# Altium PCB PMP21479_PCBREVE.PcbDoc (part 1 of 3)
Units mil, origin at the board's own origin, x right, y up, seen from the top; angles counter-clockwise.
Board outline 1915.03 x 2932.53 mil, 4 copper layers (Top Layer, Signal Layer 1, Signal Layer 2, Bottom Layer), stack 39.6 mil thick; 137 components, 82 nets, 411 pads, 91 vias.
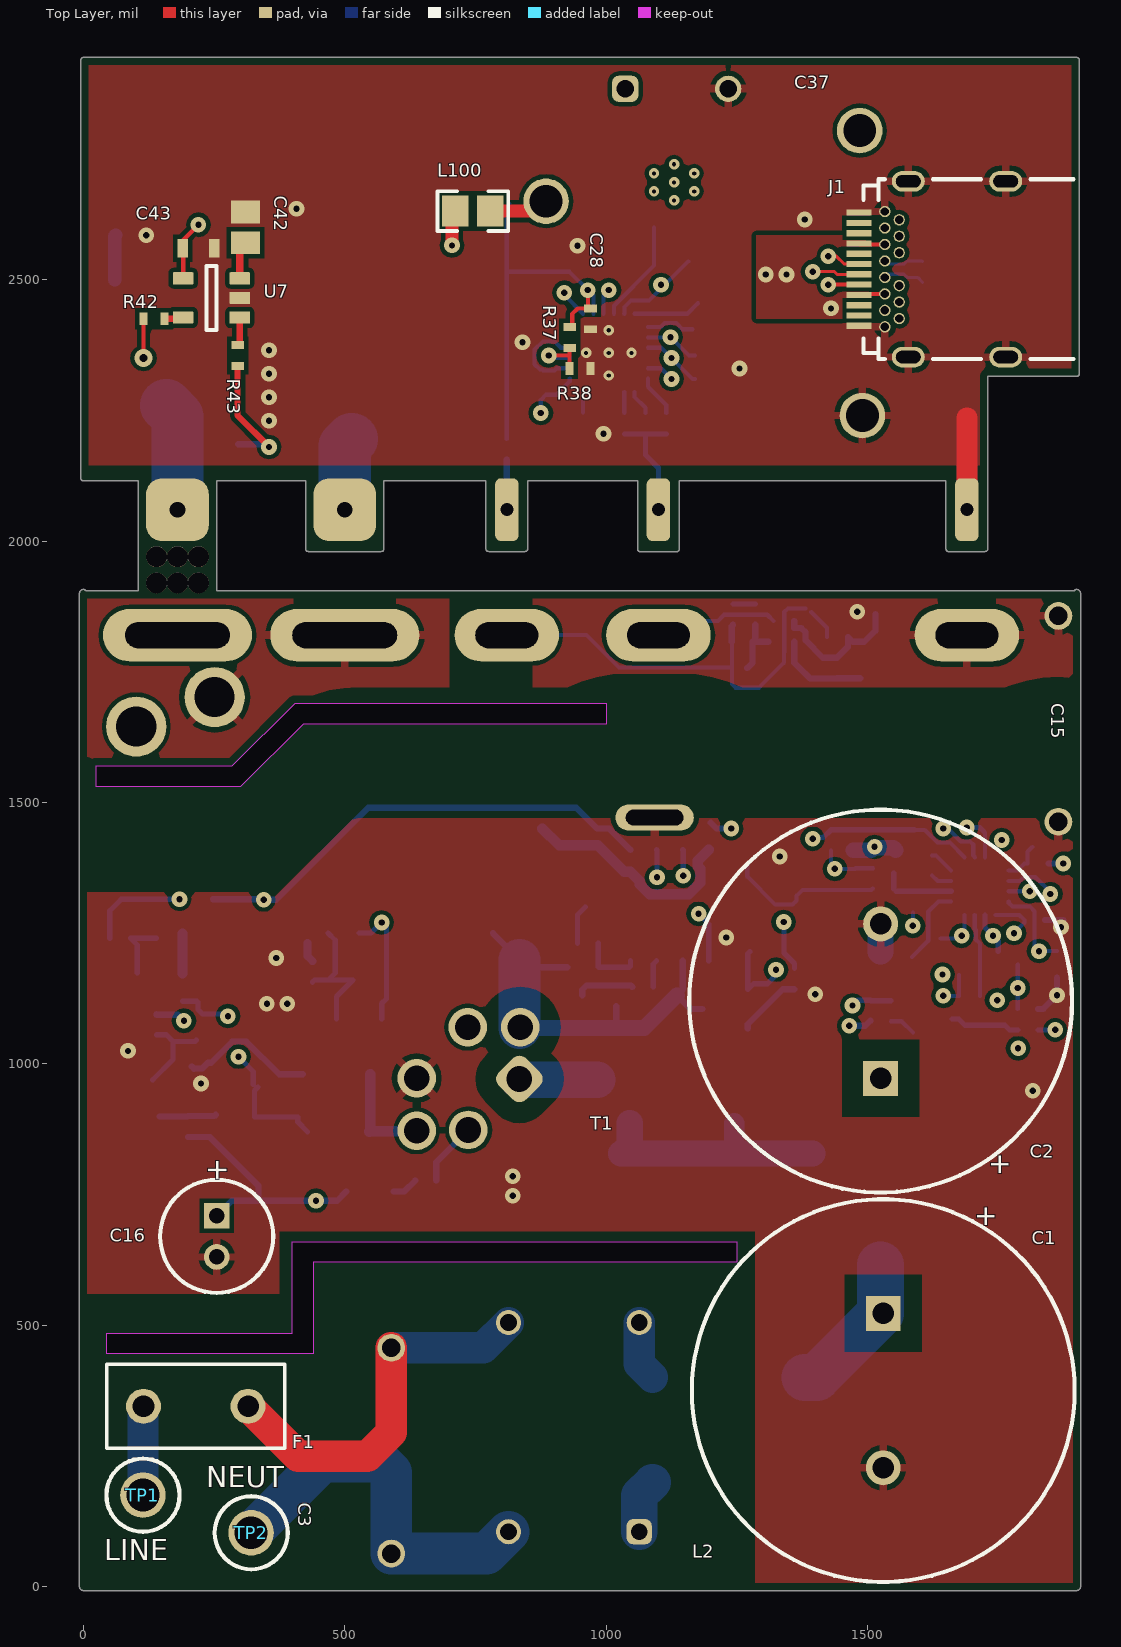
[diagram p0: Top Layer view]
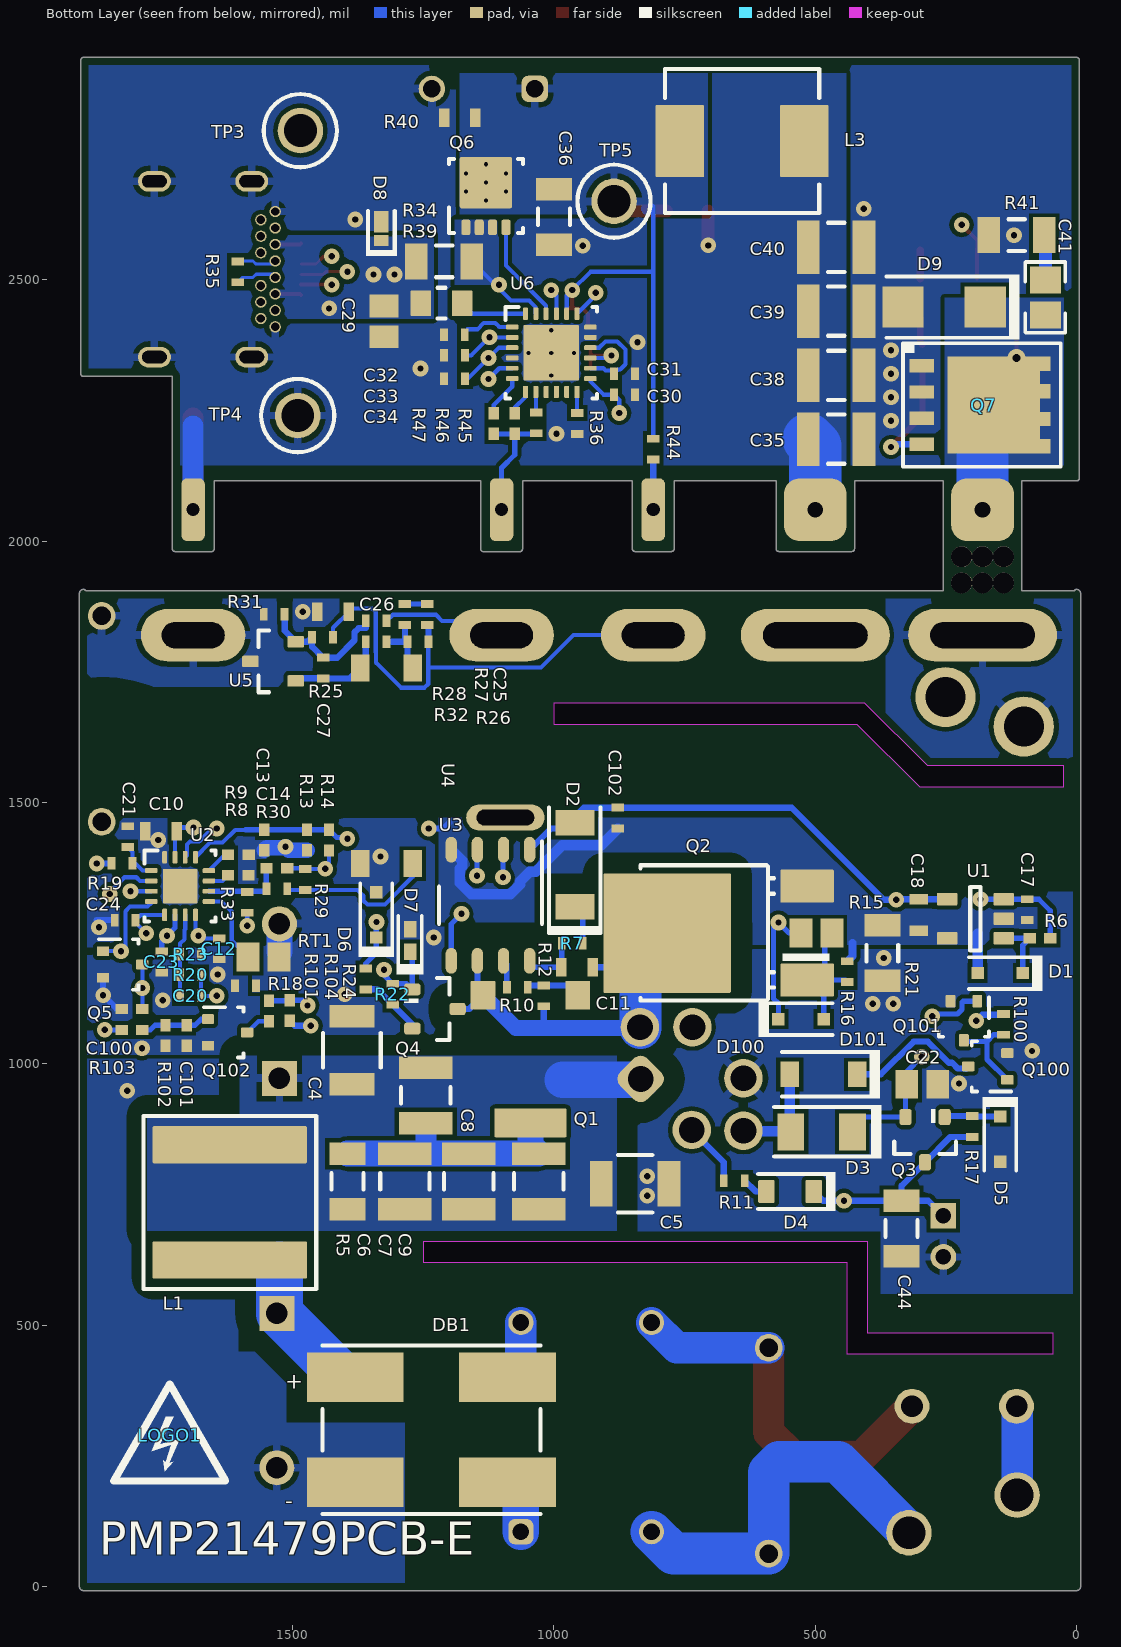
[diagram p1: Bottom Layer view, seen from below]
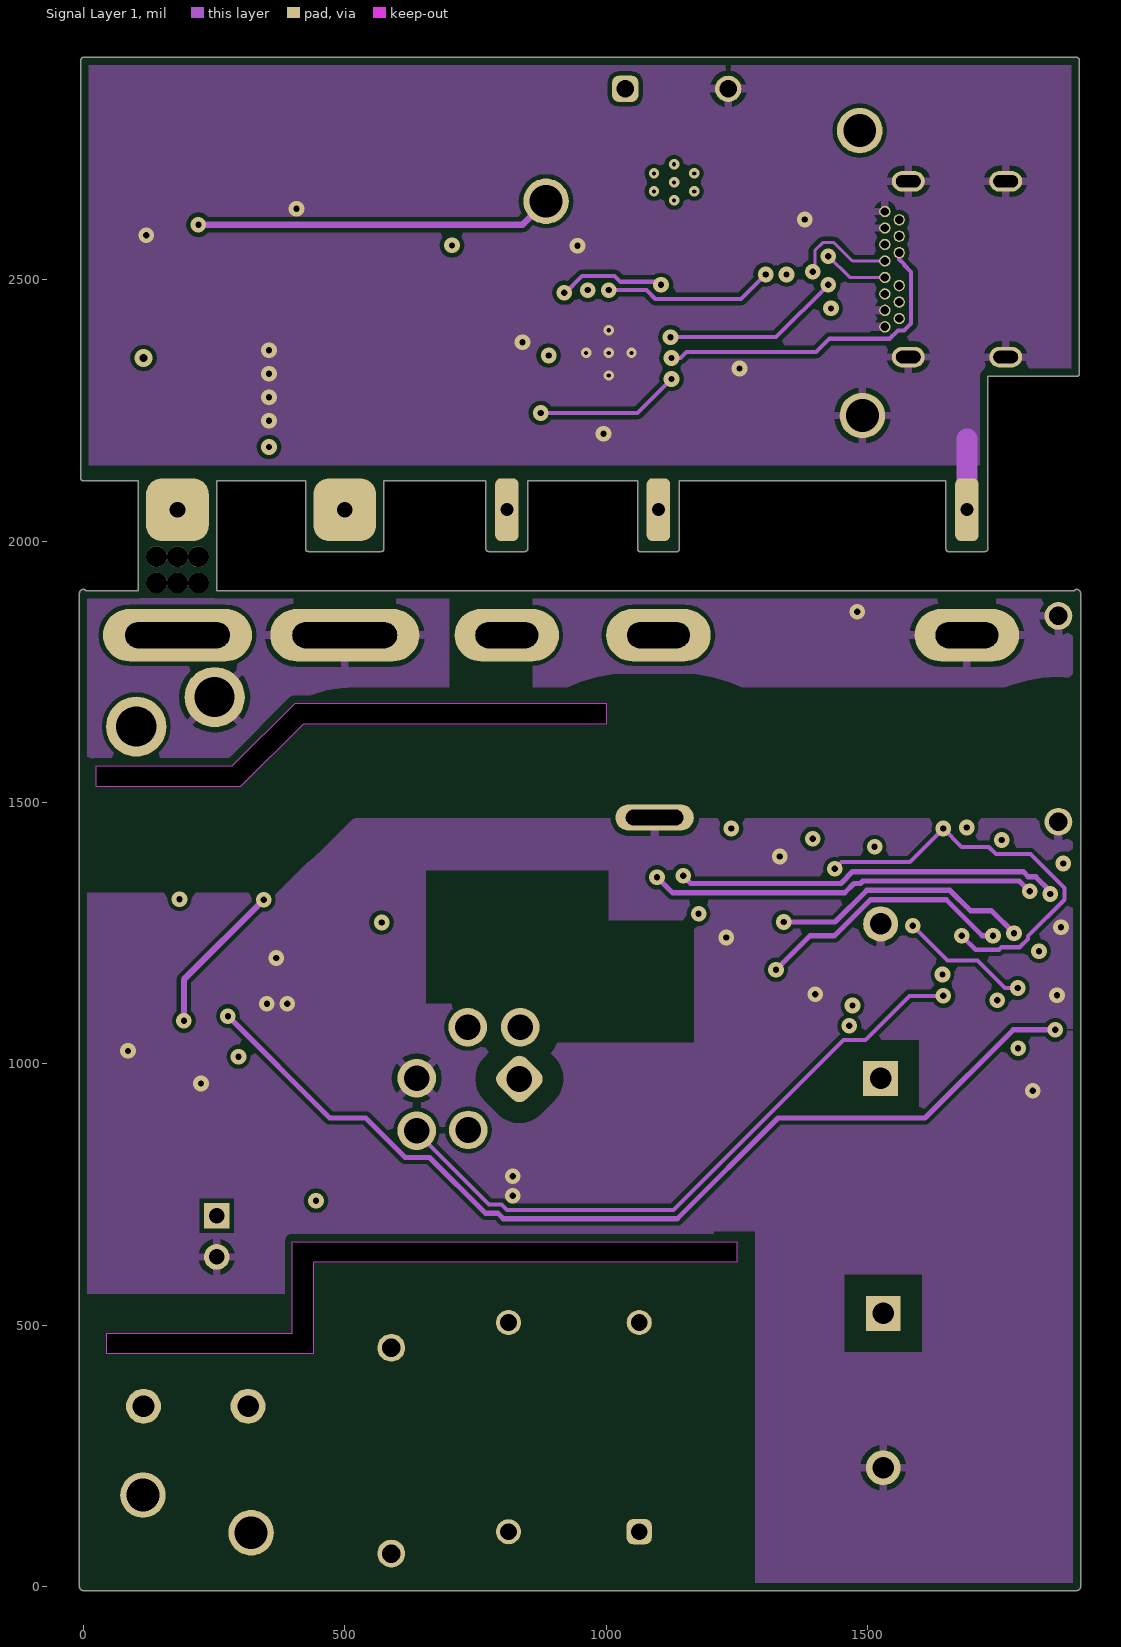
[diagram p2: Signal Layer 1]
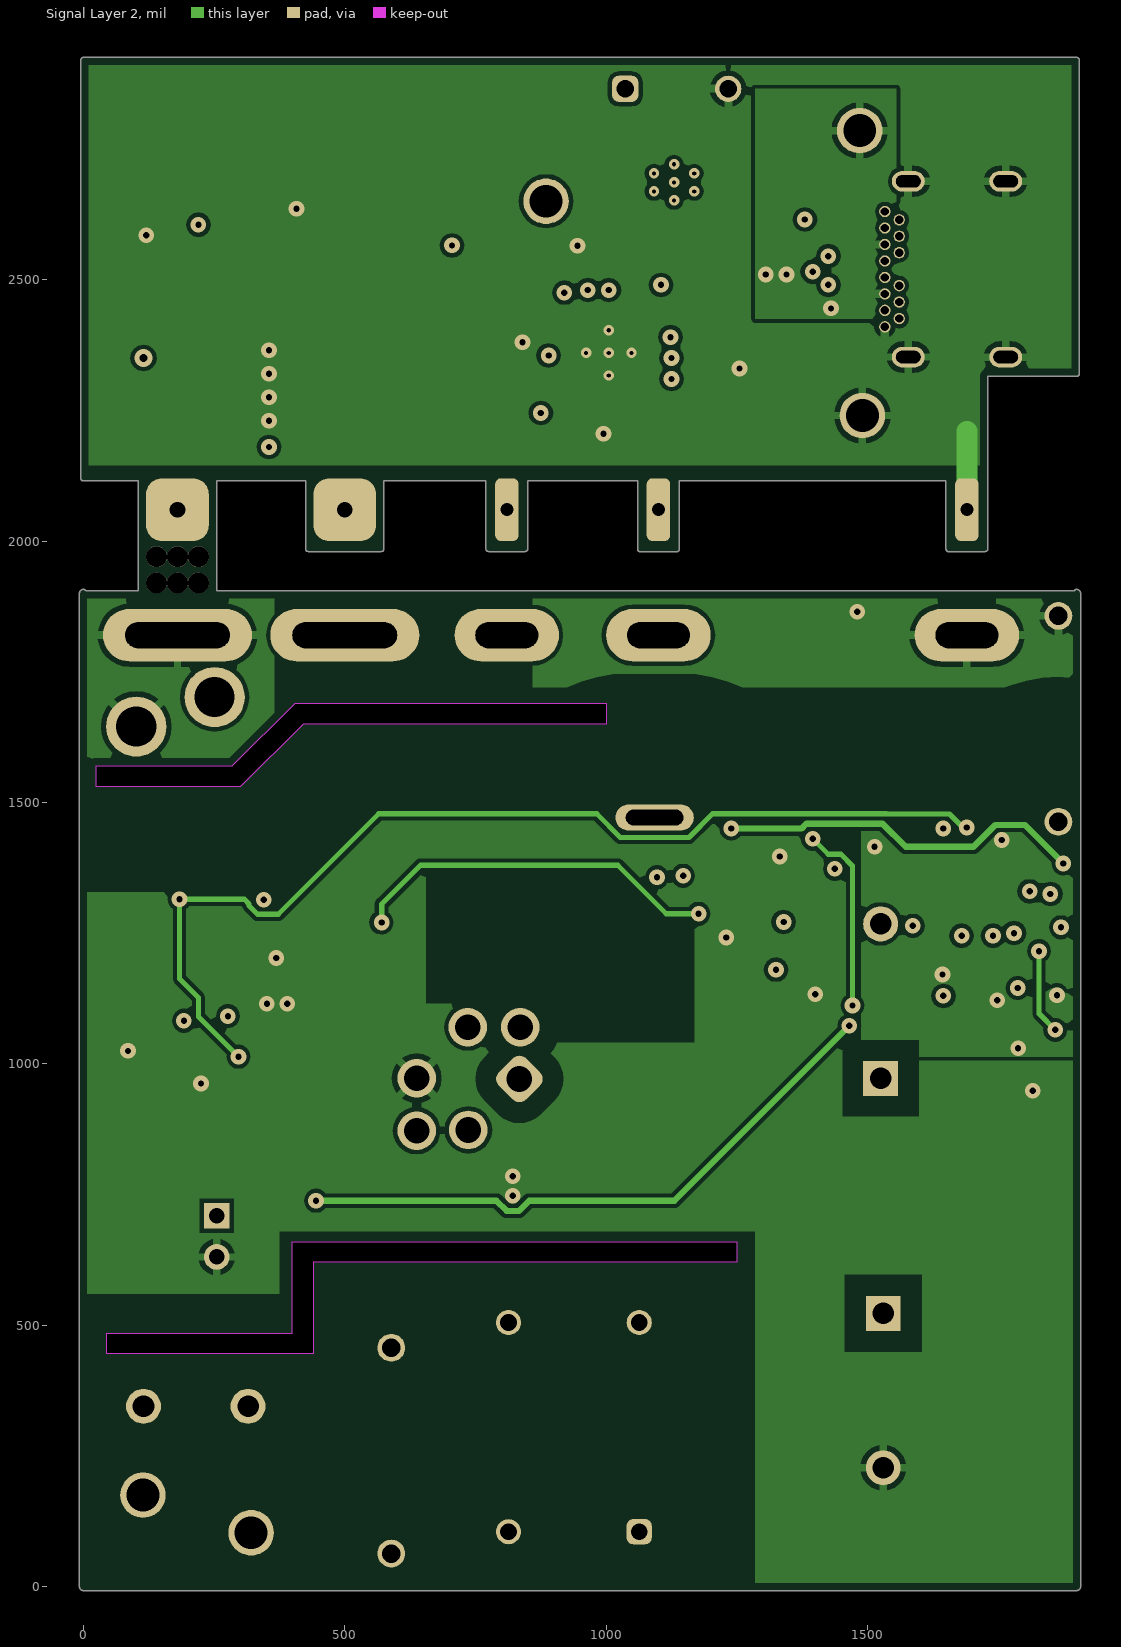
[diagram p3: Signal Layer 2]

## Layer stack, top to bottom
Top Solder: solder mask 0.4, Solder Resist, Dk 3.5
Top Layer: signal copper 1.4
Dielectric 1: prepreg 8, FR-4, Dk 4.2
Signal Layer 1: signal copper 1.4
Dielectric 2: core 18, FR-4, Dk 4.2
Signal Layer 2: signal copper 1.4
Dielectric 3: prepreg 8, FR-4, Dk 4.2
Bottom Layer: signal copper 1.4
Bottom Solder: solder mask 0.4, Solder Resist, Dk 3.5

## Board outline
0,-7.52 cw(c0,0) -7.52,0 -7.52,1900 cw(c0,1900) 0,1907.52 cw(c0,1902.5) 4.34,1905.02 104.98,1905.02 104.98,2114.98 0,2114.98 cw(c0,2120) -5.02,2120 -5.02,2920 cw(c0,2920) 0,2925.02 1900,2925.02 cw(c1900,2920) 1905.02,2920 1905.02,2320 cw(c1900,2320) 1900,2314.98 1730.02,2314.98 1730.02,1985 cw(c1725,1985) 1725,1979.98 1656.55,1979.98 cw(c1655,1984.76) 1649.98,1984.76 1649.98,2114.99 1140.02,2115.23 1140.02,1984.76 cw(c1135,1984.76) 1135,1979.74 1065,1979.74 cw(c1065,1984.76) 1059.98,1984.76 1059.98,2114.98 850.02,2114.98 850.02,1985 cw(c845,1985) 845,1979.98 775,1979.98 cw(c775,1985) 769.98,1985 769.98,2114.98 575.02,2114.98 575.02,1985 cw(c570,1985) 570,1979.98 430,1979.98 cw(c430,1985) 424.98,1985 424.98,2115.22 255.02,2114.99 255.02,1905.02 1895.66,1905.02 cw(c1900,1902.5) 1900,1907.52 cw(c1900,1900) 1907.52,1900 1907.52,0 cw(c1900,0) 1900,-7.52
cut-out: 25,1529.65 25,1570 285,1570 405,1690 1000,1690 1000,1649.65 420.35,1649.65 300.35,1529.65
cut-out: 45,445 45,485 400,485 400,660 1250,660 1250,620 440,620 440,445

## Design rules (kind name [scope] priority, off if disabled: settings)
AcuteAngle [All] p1: minimum=5.00000000000000E+0000 checktracksonly=FALSE
AssemblyTestPointUsage [All] p1: valid=2
BoardOutlineClearance BoardOutlineClearance_MountingHoles [OnCopper and InComponentClass('Mounting Holes')] p1: gap=25 ignorepadtopadclearanceinfootprint=FALSE
BoardOutlineClearance BoardOutlineClearance_Poly [OnCopper and InPoly] p2: gap=15 ignorepadtopadclearanceinfootprint=FALSE
BoardOutlineClearance [OnCopper and Not InComponentClass('Logo') and not InComponentClass('FiducialMark') and not InRegion(1000,500,4000,800)] p3: gap=15 ignorepadtopadclearanceinfootprint=FALSE
Clearance Isolation [InNetClass('Secondary') vs InNetClass('Primary')] p1: gap=250 ignorepadtopadclearanceinfootprint=FALSE
Clearance "High Voltage" [InNetClass('High Voltage') vs InNetClass('Primary')] p2: gap=40 ignorepadtopadclearanceinfootprint=FALSE
Clearance Clearance_Keepouts [((IsTrack Or IsArc) And Not InPoly) And IsFree and IsKeepOut vs ((IsTrack Or IsArc) And Not InPoly) And IsFree and IsKeepOut] p3: gap=0 ignorepadtopadclearanceinfootprint=FALSE
Clearance Clearance_Poly [InPolygon] p4: gap=8 ignorepadtopadclearanceinfootprint=FALSE except(0: Arc-Hole Track-Hole SMDPad-Hole THPad-Hole Via-Hole Fill-Hole Poly-Hole Region-Hole Text-Hole)
Clearance [All] p5: gap=7.87 ignorepadtopadclearanceinfootprint=FALSE except(0: Arc-Hole Track-Hole SMDPad-Hole THPad-Hole Via-Hole Fill-Hole Poly-Hole Region-Hole Text-Hole)
ComponentClearance ComponentClearance_MountingHoles_FiducialMarks [InComponentClass('Mounting Holes') vs InComponentClass('FiducialMark')] p1: gap=50 collisioncheckmode=3 verticalgap=10 showdistances=FALSE
ComponentClearance ComponentClearance_Shunt [InComponentClass('Header') vs InComponentClass('Shunt')] p2: gap=0 collisioncheckmode=3 verticalgap=0 showdistances=FALSE
ComponentClearance ComponentClearance_Logo [InComponentClass('Logo')] p3: gap=50 collisioncheckmode=3 verticalgap=10 showdistances=FALSE
ComponentClearance ComponentClearance_ScrewToNut [(HasFootprint('NY PMS 440 0025 PH')) vs (HasFootprint('Keystone_1902C'))] p4: gap=5 collisioncheckmode=3 verticalgap=10 showdistances=FALSE
ComponentClearance ComponentClearance_MountingHoles [InComponentClass('Mounting Holes')] p5: gap=250 collisioncheckmode=3 verticalgap=100000 showdistances=FALSE
ComponentClearance ComponentClearance_SmallPassives [HasFootprint('0201*') or HasFootprint('0402*') or HasFootprint('0508') or HasFootprint('0603*') or HasFootprint('0612') or HasFootprint('0805*') or HasFootprint('0815*') or HasFootprint('0830*') or HasFootprint('1206*') or HasFootprint('1210*') or HasFootprint('1808*') or HasFootprint('1812*') or HasFootprint('1825*') or HasFootprint('2010*') or HasFootprint('2220*') or HasFootprint('2225*') or HasFootprint('2512*') or HasFootprint('2728*') or HasFootprint('3518*') vs HasFootprint('0201*') or HasFootprint('0402*') or HasFootprint('0508') or HasFootprint('0603*') or HasFootprint('0612') or HasFootprint('0805*') or HasFootprint('0815*') or HasFootprint('0830*') or HasFootprint('1206*') or HasFootprint('1210*') or HasFootprint('1808*') or HasFootprint('1812*') or HasFootprint('1825*') or HasFootprint('2010*') or HasFootprint('2220*') or HasFootprint('2225*') or HasFootprint('2512*') or HasFootprint('2728*') or HasFootprint('3518*')] p6: gap=14.96 collisioncheckmode=3 verticalgap=10 showdistances=FALSE
ComponentClearance ComponentClearance_THtoSMT [IsThruComponent vs IsSMTComponent] p7: gap=15 collisioncheckmode=3 verticalgap=30 showdistances=FALSE
ComponentClearance ComponentClearance_THtoTH [IsThruComponent vs IsThruComponent] p8: gap=15 collisioncheckmode=3 verticalgap=30 showdistances=FALSE
ComponentClearance [All] p9: gap=15 collisioncheckmode=3 verticalgap=10 showdistances=FALSE
DiffPairsRouting [All] p1: maxlimit=100 minlimit=10 mostfreqgap=10 toplayer_minwidth=15 toplayer_maxwidth=15 toplayer_prefwidth=15 midlayer1_minwidth=15 midlayer1_maxwidth=15 midlayer1_prefwidth=15 midlayer2_minwidth=15 midlayer2_maxwidth=15 midlayer2_prefwidth=15 bottomlayer_minwidth=15 bottomlayer_maxwidth=15 bottomlayer_prefwidth=15 maxuncoupledlength=1000
FabricationTestPointUsage TestPointUsage [All] p1: valid=2 allowmultiple=FALSE
FabricationTestpoint Testpoint [All] p1: side=3 testpointundercomponent=TRUE minsize=40 maxsize=100 preferedsize=60 minholesize=0 maxholesize=40 preferedholesize=32 testpointgrid=1 allowsidetop=TRUE allowsidebottom=TRUE usegrid=TRUE gridtolerance=0.01
FanoutControl Fanout_LCC [IsLCC] p1: bgadir=Out bgaviamode=Centered fanoutstyle=Auto fanoutdirection=Alternating viagrid=1 // Fanout_LCC (Default Rule)
FanoutControl Fanout_BGA [IsBGA] p2: bgadir=Out bgaviamode=Centered fanoutstyle=Auto fanoutdirection=Alternating viagrid=1 // Fanout_BGA (Default Rule)
FanoutControl Fanout_Default [All] p4: bgadir=Out bgaviamode=Centered fanoutstyle=Auto fanoutdirection=Alternating viagrid=1 // Fanout_Default (Default Rule)
FanoutControl Fanout_Small [(CompPinCount < 5)] p5: bgadir=Out bgaviamode=Centered fanoutstyle=Auto fanoutdirection=OutThenIn viagrid=1 // Fanout_Small (Default Rule)
HoleSize [All] p1: absolutevalues=TRUE maxlimit=251 minlimit=7.87 maxpercent=80.000 minpercent=20.000
MinimumAnnularRing MinimumAnnularRing_ThermalPadVias [IsVia and InAnyComponent] p1: minimumring=5.91
MinimumAnnularRing [All] p2: minimumring=2.9
MinimumSolderMaskSliver MinimumSolderMaskSliver_Logo [InComponentClass('Logo') vs InComponentClass('Logo')] p1 off: minsoldermaskwidth=0.7
MinimumSolderMaskSliver [All] p2 off: minsoldermaskwidth=1
PlaneConnect [All] p1: planeconnectstyle=Direct reliefexpansion=10 reliefentries=4 reliefconductorwidth=10 reliefairgap=10
PolygonConnect [All] p1: thpad.connectstyle=Relief thpad.reliefconductorwidth=15 thpad.reliefentries=4 thpad.polygonreliefangle="90 Angle" thpad.airgapwidth=10 smdpad.connectstyle=Direct smdpad.reliefconductorwidth=10 smdpad.reliefentries=4 smdpad.polygonreliefangle="90 Angle" smdpad.airgapwidth=10 via.connectstyle=Direct via.reliefconductorwidth=10 via.reliefentries=4 via.polygonreliefangle="90 Angle" via.airgapwidth=10
RoutingVias ThermalPadVias [IsVia and InAnyComponent] p1: holewidth=7.87 width=19.68 viastyle="Through Hole" minholewidth=7.87 minwidth=19.68 maxholewidth=12.99 maxwidth=23.62
RoutingVias [All] p2: holewidth=16 width=34 viastyle="Through Hole" minholewidth=7.87 minwidth=26 maxholewidth=40 maxwidth=65
SilkToBoardRegionClearance [Not ((IsComment or IsDesignator) And (Hide <> 'False')) and not InRegion(1000,500,4000,800)] p1:
SilkToSilkClearance SilkToSilkClearance_Pb-FreeLogo [(HasFootprint('Pb-Free_Overlay_Medium') OR HasFootprint('Pb-Free_Overlay_Small')) vs (HasFootprint('Pb-Free_Overlay_Medium') OR HasFootprint('Pb-Free_Overlay_Small'))] p1: silktosilkclearance=0
SilkToSilkClearance [All] p2: silktosilkclearance=1
SilkToSolderMaskClearance SilkToComponentPadClearance [IsPad and InAnycomponent] p1: minsilkscreentomaskgap=0.5 clearancetoexposedcopper=TRUE
SilkToSolderMaskClearance "Silk to Solder Mask Opening" [All] p2: minsilkscreentomaskgap=0.5 clearancetoexposedcopper=FALSE
SolderMaskExpansion [All] p1: expansion=1.97
Width [All] p1: maxlimit=100 minlimit=6 preferedwidth=10 checkconnectedcopper=TRUE
15 further rules are at their usual default settings.

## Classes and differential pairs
net class Primary: ICGND NetC17_2 PGND
net class Secondary: SGND1 VDRN1 VN1
net class "High Voltage": NetC1_1 NetC6_2 NetC11_1 NetD2_1 NetQ1_1 NetR10_1 Vbulk Vswn
component class PMP21479_REVE_Secondary: C28 C29 C30 C31 C32 C33 C34 C35 C36 C37 C38 C39 C40 C41 C42 C43 D8 D9 J1 L3 L100 Q6 Q7 R34 R35 R36 R37 R38 R39 R40 R41 R42 R43 R44 R45 R46 R47 R49 R50 R51 R52 TP3 TP4 TP5 U6 U7 U8
component class PMP21479_REVE_Primary: C1 C2 C3 C4 C5 C6 C7 C8 C9 C10 C11 C12 C13 C14 C15 C16 C17 C18 C19 C20 C21 C22 C23 C24 C25 C26 C27 C44 C100 C101 C102 C? D1 D2 D3 D4 D5 D6 D7 D100 D101 D? DB1 F1 L1 L2 LOGO1 Q1 Q2 Q3 Q4 Q5 Q100 Q101 Q102 Q? R5 R6 R7 R8 R9 R10 R11 R12 R13 R14 R15 R16 R17 R18 R19 R20 R21 R22 R23 R24 R25 R26 R27 R28 R29 R30 R31 R32 R33 R100 R101 R102 R103 R104 R? RT1 T1 TP1 TP2 TP? U1 U2 U3 U4 U5 U?

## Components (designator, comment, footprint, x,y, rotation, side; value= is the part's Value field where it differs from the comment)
C1 "UCY2G560MHD3" UCY_1800x2000 1530,375 r270 top value=56uF
C2 "UCY2G560MHD3" UCY_1800x2000 1525,1120 r90 top value=56uF
C3 "890324023023" WCAP-FTX2_1300x700x1300 589,260 r270 top value=0.1uF
C4 "C1210C104KBRAC7800" 1210_280 1386.21,1025.74 r270 bottom value=0.1uF
C5 "C1210C104KBRAC7800" 1210_280 844.76,770.78 r0 bottom value=0.1uF
C6 "GRM32DR72E224KW01L" 1210_220L 1285,775 r90 bottom value=0.22uF
C7 "GRM32DR72E224KW01L" 1210_220L 1163.04,775 r90 bottom value=0.22uF
C8 "GRM32DR72E224KW01L" 1210_220L 1245,939.5 r270 bottom value=0.22uF
C9 "GRM32DR72E224KW01L" 1210_220L 1028.92,775 r90 bottom value=0.22uF
C10 "C1608X7R1E105K080AB" 0603S 1751.76,1445 r0 bottom value=1uF
C11 "GRM188R71E473KA01D" 0603S 955.79,1184.79 r180 bottom value=0.047uF
C12 "C1005X7R1H104K050BB" 0402S 1640,1220 r270 bottom value=0.1uF
C13 "GRM1555C1H101JA01D" 0402L 1553.89,1428.26 r270 bottom value=100pF
C14 "GRM1555C1H101JA01D" 0402L 1530,1374.02 r0 bottom value=100pF
C15 "DE1E3RA222MN4AN01F" DE1_900x400 1865,1659.84 r270 top value=2200pF
C16 "UPS2A4R7MDD1TD" UPW_500x1100 255,670 r270 top value=4.7uF
C17 "GRM155R71E104KE14D" 0402S 94.7,1294.91 r270 bottom value=0.1uF
C18 "C1608X7R1E105K080AB" 0603S 302.31,1284.93 r90 bottom value=1uF
C20 "GRM1555C1H3R3CA01D" 0402S 1695,1130 r0 bottom value=3.3pF
C21 "GJM1555C1H270JB01" 0402S 1815,1434.54 r90 bottom value=27pF
C22 "GRM21BC8YA106KE11L" 0805L 295.27,960.78 r0 bottom value=22uF
C23 "GRM155R71H222KA01D" 0402S 1750,1195 r270 bottom value=2200pF
C24 "GRM1555C1H240JA01D" 0402S 1820,1275 r180 bottom value=24pF
C25 "GRM155R71H183KA12D" 0402S 1242.59,1859.64 r90 bottom value=0.018uF
C26 "C1608X7R1E105K080AB" 0603S 1422.24,1864.5 r180 bottom value=1uF
C27 "GRM155R71H472KA01D" 0402S 1441.58,1757.01 r270 bottom value=4700pF
C28 "GRM155R71E104KE14D" 0402S 970,2425 r270 top value=0.1uF
C29 "GRM21BR6YA106KE43L" 0805L 1325,2420 r270 bottom value=10uF
C30 "GRM155R60J274KE01D" 0402S 865,2280 r180 bottom value=0.27uF
C31 "GRM155R71C104KA88D" 0402S 865,2320 r180 bottom value=0.1uF
C32 "GRM155R71C104KA88D" 0402S 1190.5,2394.75 r0 bottom value=0.1uF
C33 "GRM155R71H471KA01D" 0402S 1190,2355 r0 bottom value=470pF
C34 "GRM155R71H471KA01D" 0402S 1190,2310 r0 bottom value=470pF
C35 "GRM32ER71E226KE15L" 1210_270L 460,2195 r180 bottom value=22uF
C36 "GRM31MR71H224KA01L" 1206L 1000,2620 r270 bottom value=0.22uF
C37 "687AVG025MGBJ" AVG_1000x1200_HD 1135,2865 r0 top value=680uF
C38 "GRM32ER71E226KE15L" 1210_270L 460,2316.82 r180 bottom value=22uF
C39 "GRM32ER71E226KE15L" 1210_270L 460,2440 r180 bottom value=22uF
C40 "GRM32ER71E226KE15L" 1210_270L 460,2561.58 r180 bottom value=22uF
C41 "GRM21A5C2E101JW01D" 0805 60,2466.03 r90 bottom value=100pF
C42 "GRM21BR71E225KA73L" 0805L 310,2600 r270 top value=2.2uF
C43 "C1608X7R1E105K080AB" 0603S 220,2560 r0 top value=1uF
C44 "12061C104JAT2A" 1206L 335,685 r270 bottom value=0.1uF
C100 "GRM1555C1H150JA01D" 0402L 1806.83,1105 r0 bottom value=15pF
C101 "GRM1555C1H221JA01D" 0402L 1702.42,1053.97 r270 bottom value=220pF
C102 "GRM155R71E104KE14D" 0402S 877.65,1470 r270 bottom value=0.1uF
D1 "MMSZ5240BS-7-F" SOD-323 146.26,1173.62 r0 bottom value=10V
D2 "ES1JAF" SMAF 960,1380.41 r90 bottom value=600V
D3 "CSFMT104-HF" SOD-123H 487.99,870 r0 bottom value=200V
D4 "RFU02VSM8STR" TUMD2SM 548.19,755.78 r0 bottom value=800V
D5 "MMSZ5245BS-7-F" SOD-323 146.26,856.02 r270 bottom value=15V
D6 "CDSOD323-T18" SOD-323 1340,1285.1 r90 bottom value=18V
D7 "BZT52C22T-7" SOD-523 1275,1236.21 r90 bottom value=22V
D8 "NSR20F30NXT5G" DSN2_0603 1330,2600 r90 bottom value=30V
D9 "SMAJ100CA" SMA 253.74,2447.6 r0 bottom value=100V
D100 "BAS316,115" SOD-323 527.22,1085.59 r180 bottom value=100V
D101 "BAV21W-7-F" SOD-123 484.31,980 r0 bottom value=200V
DB1 "Z4DGP406L-HF" Z4-D 1234.23,300 r180 bottom value=600V
F1 "3.15A" FUSE_392 215,345 r180 top
J1 "632 723 300 011" Wurth_632_723_300_011 1900,2520 r90 top
L1 "NRS8030T220MJGJ" NRS8030 1620,735 r90 bottom value=22uH
L2 "RLTI-1301" Renco_RLTI-1301 938.19,305 r180 top value=1.3mH
L3 "0630CDMCCDS-R33MC" 0630CDMCCDS 640,2765 r0 bottom value=330nH
L100 "LBR2012T1R0M" 0805 745,2631.14 r0 top value=1uH
LOGO1 "DANGER HIGH VOLTAGE" IEC_HighVoltage_Small 1735,290 r180 bottom
Q1 "IPN70R2K0P7SATMA1" PG-SOT223 1045,1009.15 r270 bottom value=700V
Q2 "IPD60R280P7SAUMA1" DPAK 649.5,1250 r0 bottom value=600V
Q3 "BSS123" SOT-23L 290,855 r270 bottom value=100V
Q4 "BSS126H6327XTSA2" SOT-23L 1227.5,1104.92 r180 bottom value=600V
Q5 "NX3020NAKW,115" SOT-323 1825,1190 r180 bottom value=30V
Q6 "CSD17575Q3" DQG0008A 1130,2660 r90 bottom value=30V
Q7 "BSC093N15NS5ATMA1" PG-TDSON-8 185,2260 r180 bottom value=150V
Q100 "2N7002KW" SOT-323 170,995 r0 bottom value=60V
Q101 "2N7002KW" SOT-323 215.7,1082.4 r270 bottom value=60V
Q102 "2N7002KW" SOT-323 1624.17,1060 r180 bottom value=60V
R5 "CRCW12063M30JNEA" 1206L 1395,775 r270 bottom value=3.3Meg
R6 "RC0402FR-07100KL" 0402L 70.32,1240.12 r180 bottom value=100k
R7 "CRCW04024R70JNED" 0402S 965,1230.73 r0 bottom value=4.7
R8 "CRCW0402200KFKED" 0402L 1603.8,1360.52 r0 bottom value=200k
R9 "CRCW0402130KFKED" 0402L 1603.67,1400 r0 bottom value=130k
R10 "CRCW040215R0JNED" 0402S 1070,1146.9 r180 bottom value=15
R11 "CRCW04020000Z0ED" 0402S 655,776.69 r180 bottom value=0
R12 "CRCW040210K0JNED" 0402S 1019.18,1130 r90 bottom value=10k
R13 "CRCW040248K7FKED" 0402L 1472.39,1428.13 r90 bottom value=48.7k
R14 "CRCW0402200KFKED" 0402L 1430,1427.88 r270 bottom value=200k
R15 "CRCW080547R0JNEA" 0805L 497.69,1250 r180 bottom value=47
R16 "CRCW040210K0JNED" 0402S 438.51,1176.22 r270 bottom value=10k
R17 "CRCW04021M00JNED" 0402S 200,880 r90 bottom value=1.0Meg
R18 "CRCW04020000Z0ED" 0402S 1589.76,1149.07 r0 bottom value=0
R19 "CRCW04021K78FKED" 0402S 1826.14,1383.31 r0 bottom value=1.78k
R20 "CRCW040256K2FKED" 0402S 1695,1170 r180 bottom value=56.2k
R21 "ERJ-8BSFR15V" 1206L 371.87,1211.82 r90 bottom value=0.15
R22 "ERJ-2RKF1373X" 0402S 1308.42,1133.28 r90 bottom value=137k
R23 "CRCW040213K3FKED" 0402S 1695,1210 r0 bottom value=13.3k
R24 "CRCW0402118RFKED" 0402S 1360,1162.4 r270 bottom value=118
R25 "ERJ-2RKF1503X" 0402S 1442.55,1816.15 r180 bottom value=150k
R26 "CRCW04023K01FKED" 0402S 1260,1807.5 r180 bottom value=3.01k
R27 "CRCW0402150RFKED" 0402S 1285,1859.64 r90 bottom value=150
R28 "CRCW040224K9FKED" 0402S 1340,1847.15 r0 bottom value=24.9k
R29 "CRCW04021M00JNED" 0402S 1476.03,1352.58 r90 bottom value=1.0Meg
R30 "CRCW040239K2FKED" 0402S 1530,1335 r180 bottom value=39.2k
R31 "ERJ-2RKF1503X" 0402S 1535,1860 r0 bottom value=150k
R32 "CRCW040215K0FKED" 0402S 1340,1807.6 r180 bottom value=15.0k
R33 "CRCW0402511KFKED" 0402S 1586.76,1308.97 r90 bottom value=511k
R34 "WSL12065L000FEA" 1206L 1210,2535 r180 bottom value=0.005
R35 "CRCW0402100RJNED" 0402S 1605,2515 r90 bottom value=100
R36 "CRCW0402100KFKED" 0402S 955,2225 r90 bottom value=100k
R37 "CRCW0402140KFKED" 0402S 930.2,2389.53 r90 top value=140k
R38 "CRCW040286K6FKED" 0402S 950,2330 r180 top value=86.6k
R39 "RG2012P-121-B-T5" 0805_HV1 1215,2455 r0 bottom value=120
R40 "CRCW060310M0JNEA" 0603S 1180,2809.8 r180 bottom value=10Meg
R41 "CRCW12061K00JNEA" 1206L 115,2585 r180 bottom value=1.0k
R42 "CRCW040210R0JNED" 0402S 135,2425 r180 top value=10
R43 "CRCW040210R0JNED" 0402S 295,2355 r270 top value=10
R44 "RC0402JR-070RL" 0402S 810,2175.79 r270 bottom value=0
R45 "RC0402JR-070RL" 0402S 1033.58,2226.03 r270 bottom value=0
R46 "CRCW040269K8FKED" 0402L 1075,2225 r90 bottom value=69.8k
R47 "CRCW040215K0FKED" 0402L 1115,2225 r90 bottom value=15.0k
R100 "CRCW040210K0JNED" 0402S 140,1075.5 r90 bottom value=10k
R101 "CRCW0402100KFKED" 0402L 1545,1101.18 r90 bottom value=100k
R102 "CRCW0402200KFKED" 0402L 1742.95,1053.97 r90 bottom value=200k
R103 "CRCW0402301KFKED" 0402L 1806.83,1064.63 r0 bottom value=301k
R104 "CRCW04021M00FKED" 0402L 1505.5,1102.13 r270 bottom value=1.00Meg
RT1 "NCP21WF104J03RA" 0805L 1555.47,1204.4 r180 bottom value=100k
T1 "RLTI-1273" Renco_RLTI-1273 486.1,1221.43 r225 top locked value=110uH
TP1 "LINE" Keystone5011 114,175 r270 top
TP2 "NEUTRAL" Keystone5012 321,103 r270 top
TP3 "VBUS" Keystone5010 1485,2785 r180 bottom
TP4 "SGND" Keystone5011 1490,2240 r180 bottom
TP5 "Vout" Keystone5010 885,2650 r180 bottom
U1 "TPS7B4250QDBVRQ1" DBV0005A_N 193.75,1277.52 r0 bottom
U2 "UCC28780RTER" RTE0016C_NV 1715,1340 r180 bottom
U3 "UCC27710DR" D0008B_L 1121.32,1303.36 r270 bottom
U4 "VOL618A-2T" SOP254P1020X230-4 1320,1570 r270 bottom
U5 "ATL431AIDBZR" DBZ0003A_L 1537.19,1769.87 r0 bottom
U6 "TPS25740BRGER" RGE0024H 1005,2360 r180 bottom
U7 "UCC24612-2DBVT" DBV0005A_N 245,2465 r180 top

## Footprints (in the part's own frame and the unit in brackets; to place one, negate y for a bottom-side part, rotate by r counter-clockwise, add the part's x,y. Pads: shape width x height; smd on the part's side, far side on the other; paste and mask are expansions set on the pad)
0402L [mm] "0402 from SM-752 data"
  rect 0.6x0.5 smd: 1(-0.5,0) 2(0.5,0)
  body extent -0.55,-0.3 0.55,0.3, height 0.6
0402S [mil] "Based on C0402S footprint from PADS legacy"
  rect 15x24 smd: 1(-20,0) 2(20,0)
  body extent -22,-12 22,12, height 24
0603S [mil]
  rect 20x35 smd: 1(-30,0) 2(30,0)
  body extent -34,-19 34,19, height 39
0630CDMCCDS [mm] "SMD, 2-Leads, Body 7x6.6mm"
  rrect4% 2.35x3.5 smd: 1(-3.025,0) 2(3.025,0)
  silkscreen extent -3.75,-3.5 3.75,3.5, body extent -3.65,-3.4 3.65,3.4, height 3
0805 [mm] "0805 from SM-752 data"
  rect 1.3x1.5 smd: 1(-0.85,0) 2(0.85,0)
  silkscreen extent -1.72,-0.97 1.72,0.97, body extent -1.1,-0.72 1.1,0.72, height 1.45
0805_HV1 [mm] "Custom footprint based on analyzing multiple manufacturer recommendations"
  rrect10% 1x1.25 smd: 1(-1,0) 2(1,0)
  silkscreen extent -0.2,-0.75 0.2,0.75, body extent -1.1,-0.72 1.1,0.73, height 1.45
0805L [mm] "0805 from SM-752 data"
  rect 1.1x1.4 smd: 1(-0.75,0) 2(0.75,0)
  body extent -1.1,-0.72 1.1,0.72, height 1.45
1206L [mm] "1206 from SM-752 data"
  rect 1.1x1.75 smd: 1(-1.35,0) 2(1.35,0)
  silkscreen extent -0.4,-0.77 0.4,0.77, body extent -1.7,-0.9 1.7,0.9, height 1.35
1210_220L [mm] "1210"
  rect 1.1x2.6 smd: 1(-1.35,0) 2(1.35,0)
  silkscreen extent -0.4,-1.2 0.4,1.2, body extent -1.7,-1.35 1.7,1.35, height 2.2
1210_270L [mm] "1210"
  rect 1.1x2.6 smd: 1(-1.35,0) 2(1.35,0)
  silkscreen extent -0.4,-1.2 0.4,1.2, body extent -1.7,-1.35 1.7,1.35, height 2.7
1210_280 [mm] "SMD, 2-Leads, Body 3.6x2.8mm, Height 2.8mm"
  rect 1.1x2.2 smd: 1(-1.65,0) 2(1.65,0)
  silkscreen extent -0.84,-1.4 0.84,1.4, body extent -1.8,-1.4 1.8,1.4, height 2.8
AVG_1000x1200_HD [mm] "TH, 2-Leads, Dia 10mm, Pin Spacing 5mm"
  rrect50% 1.275x1.275 hole 0.85: 1(-2.5,0)
  round 1.275 hole 0.85: 2(2.5,0)
  body extent -5.25,-15.25 5.25,0.31, height 10.5
D0008B_L [mm] "SOIC, 8-Leads, Body 4.9x3.9mm, Pitch 1.27mm, IPC High Density"
  oval 1.25x0.55 smd: 1(-2.7,1.905) 2(-2.7,0.635) 3(-2.7,-0.635) 4(-2.7,-1.905) 5(2.7,-1.905) 6(2.7,-0.635) 7(2.7,0.635) 8(2.7,1.905)
  silkscreen extent -3.1,-2.5 0.9,2.5, body extent -3,-2.45 3,2.45, height 1.63
DBV0005A_N [mm] "SOT23, 5-Leads, Body 2.9x1.6mm, Pitch 0.95mm, Lead Span 2.8mm, IPC Medium Density"
  rrect17% 1x0.6 smd: 1(-1.375,0.95) 2(-1.375,0) 3(-1.375,-0.95) 4(1.375,-0.95) 5(1.375,0.95)
  silkscreen extent -0.25,-1.55 0.25,1.55, body extent -1.42,-1.46 1.42,1.46, height 1.09
DBZ0003A_L [mm] "SOT23, 3-Leads, Body 2.9x1.3mm, Pitch 0.95mm, Lead Span 2.4mm, IPC High Density"
  rrect18% 0.8x0.55 smd: 1(-1.1,0.95) 2(-1.1,-0.95) 3(1.1,0)
  silkscreen extent 0.2,-1.5 0.7,1.5, body extent -1.26,-1.46 1.26,1.46, height 0.98
DE1_900x400 [mm] "TH, 2-Leads, Dia 9mm, Lead Spacing 10mm"
  round 1.35 hole 0.9: 1(-5,0) 2(5,0)
  body extent -5.3,-2 5.3,2, height 11.5
DPAK [mm] "D-PAK, 3-Pads, Body 6.22x6.73mm (max), TO-252AA using nominal STEP model"
  rrect6% 2.6x1.6 smd: 1(-3.4,2.28) 3(-3.4,-2.28)
  rrect2% 6.2x5.8 smd paste-2.9: 4(3.4,0)
  silkscreen extent -4.5,-3.3 4.7,3.28, body extent -3.86,-3.29 5.84,3.29, height 2.48
DQG0008A [mm] "SMD, 8-Leads, Body 3.3x3.3mm, Pitch 0.65mm"
  rrect45% 0.75x0.44 smd paste-0.05 mask-0.05: 1(-1.525,0.975) 2(-1.525,0.325) 3(-1.525,-0.325) 4(-1.525,-0.975) 5(1.525,-0.975) 6(1.525,-0.325) 7(1.525,0.325) 8(1.525,0.975)
  rrect15% 0.676x1.125 on Bottom Paste: 9(-0.212,-0.663) 9(-0.212,0.662) 9(0.664,-0.663) 9(0.664,0.662)
  rrect6% 1.775x2.45 on Bottom Solder: 9(0.327,0)
  rrect8% 2.5x2.55 smd paste-1.5 mask-1.5: 9(0.65,0)
  rrect29% 0.5x0.34 on Bottom Solder: 9(1.175,-0.975) 9(1.175,-0.325) 9(1.175,0.325) 9(1.175,0.975)
  silkscreen extent -1.8,-1.8 1.8,1.8, body extent -1.65,-1.65 1.65,1.65, height 1.1
DSN2_0603 [mm] "SMD, 2-Leads, Body 1.6x0.8mm"
  rect 0.52x0.7 smd: 1(-0.64,0)
  rect 1.05x0.7 smd: 2(0.275,0)
  silkscreen extent -1.4,-0.75 0.8,0.75, body extent -0.8,-0.4 0.8,0.4, height 0.31
FUSE_392 [mm] "LITTELFUSE"
  round 1.7 hole 1.05: 1(-2.54,0) 2(2.54,0)
  silkscreen extent -4.32,-2.03 4.32,2.03, body extent -4.25,-2 4.25,2, height 8
IEC_HighVoltage_Small [mil]
  silkscreen extent -107,-88 107,97
Keystone5010 [mil] "Keystone Multipurpose loops"
  round 87 hole 63: 1(0,0)
  silkscreen extent -70,-70 70,70, body extent -63,-63 63,62, height 319
Keystone5011 [mil] "Keystone Multipurpose loops"
  round 87 hole 63: 1(0,0)
  silkscreen extent -70,-70 70,70, body extent -63,-63 63,62, height 319
Keystone5012 [mil] "Keystone Multipurpose loops"
  round 87 hole 63: 1(0,0)
  silkscreen extent -70,-70 70,70, body extent -63,-63 63,62, height 319
NRS8030 [mm] "SMD, 2-Leads, Body 8x8mm"
  rrect6% 1.8x7.5 smd: 1(-2.8,0) 2(2.8,0)
  silkscreen extent -4.2,-4.2 4.2,4.2, body extent -4.1,-4.1 4.1,4.1, height 3
PG-SOT223 [mm] "SMD, 3-Leads, Body 7x6.5mm"
  rrect8% 1.4x1.2 smd: 1(-3.1,2.3) 3(-3.1,-2.3)
  rrect7% 1.4x3.5 smd: 2(3.1,0)
  body extent -3.5,-3.25 3.5,3.25, height 1.8
PG-TDSON-8 [mm] "Infineon recommended land pattern"
  rect 1.2x0.65 smd: 1(-2.825,1.905) 2(-2.825,0.635) 3(-2.825,-0.635) 4(-2.825,-1.905)
  rect 0.5x0.7 smd: 5(3.175,-2) 6(3.175,-0.675) 7(3.175,0.675) 8(3.175,2)
  rect 4.5x4.7 smd paste-2.25: 9(0.675,0)
  silkscreen extent -3.74,-3 3.93,3, body extent -3.18,-2.89 3.18,2.9, height 1.1
Renco_RLTI-1273 [mm] "Transformer, 110 uH, TH"
  rrect50% 1.875x1.875 hole 1.25: 1(-1.753,10.744)
  round 1.875 hole 1.25: 2(-3.556,8.992) 3(-1.753,7.188) 5(1.753,10.744) 6(3.556,8.992) 7(1.753,7.188)
  round 2.925 hole 1.95: A(-4.4,-12.842) B(-0.693,-14.522)
  body extent -15.17,-15.08 15.07,15.16, height 16.89
Renco_RLTI-1301 [mil] "TH, 4-Leads, Body 15.24x9.906mm"
  rrect50% 48x48 hole 32: 1(-125,200)
  round 48 hole 32: 2(125,200) 3(-125,-200) 4(125,-200)
  body extent -195,-300 195,300, height 725
RGE0024H [mm] "QFN, 24-Leads, Body 4x4mm, Pitch 0.5mm, Thermal Pad 2.7x2.7mm, TI Recommended"
  rrect42% 0.6x0.24 smd: 1(-1.9,1.25) 2(-1.9,0.75) 3(-1.9,0.25) 4(-1.9,-0.25) 5(-1.9,-0.75) 6(-1.9,-1.25) 13(1.9,-1.25) 14(1.9,-0.75) 15(1.9,-0.25) 16(1.9,0.25) 17(1.9,0.75) 18(1.9,1.25)
  rrect42% 0.24x0.6 smd: 7(-1.25,-1.9) 8(-0.75,-1.9) 9(-0.25,-1.9) 10(0.25,-1.9) 11(0.75,-1.9) 12(1.25,-1.9) 19(1.25,1.9) 20(0.75,1.9) 21(0.25,1.9) 22(-0.25,1.9) 23(-0.75,1.9) 24(-1.25,1.9)
  rrect8% 1.19x1.19 on Bottom Paste: 25(-0.695,-0.695) 25(-0.695,0.695) 25(0.695,-0.695) 25(0.695,0.695)
  rrect4% 2.7x2.7 smd paste-1.35: 25(0,0)
  silkscreen extent -2.22,-2.22 2.22,2.22, body extent -2.07,-2.07 2.07,2.07, height 1.01
RTE0016C_NV [mm] "Texas Insturments"
  rrect42% 0.6x0.24 smd: 1(-1.4,0.75) 2(-1.4,0.25) 3(-1.4,-0.25) 4(-1.4,-0.75) 9(1.4,-0.75) 10(1.4,-0.25) 11(1.4,0.25) 12(1.4,0.75)
  rrect42% 0.24x0.6 smd: 5(-0.75,-1.4) 6(-0.25,-1.4) 7(0.25,-1.4) 8(0.75,-1.4) 13(0.75,1.4) 14(0.25,1.4) 15(-0.25,1.4) 16(-0.75,1.4)
  rrect6% 1.55x1.55 on Bottom Paste: 17(0,0)
  rrect6% 1.68x1.68 smd paste-0.85: 17(0,0)
  silkscreen extent -1.72,-1.73 1.72,1.73, body extent -1.57,-1.57 1.58,1.58, height 0.81
SMA [mm] "Molded Diode, 2-Leads, Body 4.3x2.6mm, IPC Medium Density, based on OnSemi component dimensions and land pattern"
  rect 2x2 smd: 1(-2,0) 2(2,0)
  silkscreen extent -3.66,-1.57 2.79,1.57, body extent -2.6,-1.3 2.6,1.3, height 2.42
SMAF [mm] "SMD, 2-Leads, Body 3.8x2.5mm"
  rect 1.24x1.89 smd: 1(-2.04,0) 2(2.04,0)
  silkscreen extent -3.4,-1.3 2.8,1.3, body extent -2.35,-1.25 2.35,1.25, height 1
SOD-123 [mm] "On Semi recommended land pattern"
  rect 0.915x1.22 smd: 1(-1.637,0) 2(1.637,0)
  silkscreen extent -2.74,-1.17 2.03,1.17, body extent -1.93,-0.9 1.93,0.9, height 1.35
SOD-123H [mm] "SMT, 2-Leads, Body 3.5x1.6mm"
  rect 1.3x1.8 smd: 1(-1.5,0) 2(1.5,0)
  silkscreen extent -2.9,-1.3 2.3,1.3, body extent -1.9,-0.9 1.9,0.9, height 1
SOD-323 [mm] "NXP recommended land pattern"
  rect 0.6x0.6 smd paste-0.05: 1(-1.1,0) 2(1.1,0)
  silkscreen extent -2.06,-0.86 1.53,0.86, body extent -1.3,-0.67 1.3,0.68, height 1.1
SOD-523 [mm] "NXP Semiconductor recommended land pattern, nominal STEP model"
  rect 0.8x0.6 smd paste-0.05: 1(-0.55,0) 2(0.55,0)
  silkscreen extent -1.65,-0.66 1.2,0.66, body extent -0.8,-0.4 0.8,0.4, height 0.72
SOP254P1020X230-4 [mm] "VISHAY"
  rect 1.3x0.9 smd: 1(-4.75,1.27) 2(-4.75,-1.27) 3(4.75,-1.27) 4(4.75,1.27)
  body extent -3.85,-2.05 3.85,2.05, height 2.02
SOT-23L [mm] "SOT23, 3-Leads, Body 2.9x1.3mm, Pitch 0.95mm, Lead Span 2.5mm, IPC High Density"
  rrect50% 0.8x0.6 smd: 1(-1.1,0.95) 2(-1.1,-0.95) 3(1.1,0)
  silkscreen extent -1.5,-1.5 0.7,1.5, body extent -1.16,-1.45 1.21,1.45, height 1
SOT-323 [mm] "Diodes Inc recommended land pattern.  2016-02-24"
  rrect21% 0.6x0.47 smd: 1(-0.95,0.65) 2(-0.95,-0.65) 3(0.95,0)
  silkscreen extent -1.14,-1.22 0.77,1.22, body extent -1.13,-1.13 1.12,1.12, height 1.13
TUMD2SM [mm] "SMD, 2-Leads, Body 2x1.4mm"
  rrect12% 0.8x1.1 smd: 1(-1.15,0) 2(1.15,0)
  silkscreen extent -2.2,-0.95 1.55,0.95, body extent -1.35,-0.75 1.35,0.75, height 0.8
UCY_1800x2000 [mm] "Nichicon"
  rect 1.7x1.7 hole 1.05: 1(-3.75,0)
  round 1.7 hole 1.05: 2(3.75,0)
  silkscreen extent -9.3,-9.3 9.3,9.3, body extent -9.25,-9.25 9.26,9.25, height 21.51
UPW_500x1100 [mm] "TH, 2-Leads, Dia 5mm,  Lead Spacing 2mm"
  rect 1.25x1.25 hole 0.75: 1(-1,0)
  round 1.25 hole 0.75: 2(1,0)
  silkscreen extent -2.75,-2.75 2.75,2.75, body extent -2.73,-2.75 2.75,2.75, height 12.51
WCAP-FTX2_1300x700x1300 [mm] "TH, 2-Leads, Body 13x7mm, Pin Spacing 10mm"
  round 1.35 hole 0.9: 1(-5,0) 2(5,0)
  body extent -6.5,-3.5 6.5,3.5, height 13
Wurth_632_723_300_011 [mm] "Connector, Receptacle, USB Type C, R/A"
  rect 0.3x1.2 smd: A1(-2.75,10.58) A2(-2.25,10.58) A3(-1.75,10.58) A4(-1.25,10.58) A5(-0.75,10.58) A6(-0.25,10.58) A7(0.25,10.58) A8(0.75,10.58) A9(1.25,10.58) A10(1.75,10.58) A11(2.25,10.58) A12(2.75,10.58)
  round 0.55 hole 0.4: B1(2.8,9.32) B2(2.4,8.62) B3(1.6,8.62) B4(1.2,9.32) B5(0.8,8.62) B6(0.4,9.32) B7(-0.4,9.32) B8(-0.8,8.62) B9(-1.2,9.32) B10(-1.6,8.62) B11(-2.4,8.62) B12(-2.8,9.32) M1(2,9.32) M2(-2,9.32)
  rrect100% 1x1.6 hole 0.6 slot 1.2 at 90 deg: S1(-4.27,8.18) S2(-4.27,3.45) S3(4.27,3.45) S4(4.27,8.18)
  silkscreen extent -4.37,0.15 4.37,10.36, body extent -4.37,-0.96 4.37,10.83, height 3.07
Z4-D [mm] "SMD, 4-Leads, Body 8.1x10.5mm"
  rect 4.7x2.4 smd: 1(-3.7,2.55) 2(3.7,2.55) 3(3.7,-2.55) 4(-3.7,-2.55)
  silkscreen extent -5.3,-4.1 5.3,4.1, body extent -5.3,-4.1 5.3,4.1, height 1.56

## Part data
C1 C2: library part CMP-0086273-1, "CAP, AL, 56 µF, 400 V, +/- 20%, AEC-Q200 Grade 2, TH", Cap_Case=18x20mm, Manufacturer=Nichicon, Tolerance_%=20%, Value2=400V, ValueDisplayed=56µF
C3: library part CMP-0081647-1, "CAP, Film, 0.1 µF,  V,+/- 10%, TH", Cap_Case=13x7x13mm, Manufacturer="Wurth Elektronik", Supplier Part Number 1=732-5883-ND, Tolerance_%=10%, ValueDisplayed=0.1µF
C4 C5: library part CMP-0009076-1, "CAP, CERM, 0.1 uF, 630 V, +/- 10%, X7R, 1210", Cap_Case=1210, Manufacturer=Kemet, Supplier Part Number 1=399-13490-1-ND, TempCo=X7R, Tolerance_%=10%, Value1=Unknown, Value2=630V, ValueDisplayed=0.1uF
C6 C7 C8 C9: library part CMP-0009193-2, "CAP, CERM, 0.22 uF, 250 V, +/- 10%, X7R, 1210", Cap_Case=1210, Manufacturer=MuRata, Supplier Part Number 1=490-3545-1-ND, TempCo=X7R, Tolerance_%=10%, Value1=Unknown, Value2=250V, ValueDisplayed=0.22uF
C10 C18 C26 C43: library part CMP-0007040-4, "CAP, CERM, 1 uF, 25 V, +/- 10%, X7R, 0603", Cap_Case=0603, Manufacturer=TDK, Supplier Part Number 1=445-5956-1-ND, TempCo=X7R, Tolerance_%=10%, Value1=Unknown, Value2=25V, ValueDisplayed=1uF
C11: library part CMP-0007423-4, "CAP, CERM, 0.047 uF, 25 V, +/- 10%, X7R, 0603", Cap_Case=0603, Manufacturer=MuRata, Supplier Part Number 1=490-1522-1-ND, TempCo=X7R, Tolerance_%=10%, Value1=Unknown, Value2=25V, ValueDisplayed=0.047uF
C12: library part CMP-0006297-2, "CAP, CERM, 0.1 uF, 50 V, +/- 10%, X7R, 0402", Cap_Case=0402, Manufacturer=TDK, Supplier Part Number 1=445-5932-1-ND, TempCo=X7R, Tolerance_%=10%, Value1="0.039064 ohm", Value2=50V, ValueDisplayed=0.1uF
C13 C14: library part CMP-0006410-2, "CAP, CERM, 100 pF, 50 V, +/- 5%, C0G/NP0, 0402", Cap_Case=0402, Manufacturer=MuRata, Supplier Part Number 1=81-GRM1555C1H101JA1D, TempCo=C0G/NP0, Tolerance_%=5%, Value1=Unknown, Value2=50V, ValueDisplayed=100pF
C15: library part CMP-0086279-1, "CAP, CERM, 2200 pF, 250 V,+/- 20%, E, Dia 9mm", Cap_Case=9x4mm, Manufacturer=MuRata, TempCo=E, Tolerance_%=20%, Value2=250V, ValueDisplayed=2200pF
C16: library part CMP-0084595-1, "CAP, AL, 4.7 µF, 100 V, +/- 20%, TH", Cap_Case=5x11mm, Manufacturer=Nichicon, Tolerance_%=20%, Value2=100V, ValueDisplayed=4.7µF
C17 C28 C102: library part CMP-0006659-2, "CAP, CERM, 0.1 uF, 25 V, +/- 10%, X7R, 0402", Cap_Case=0402, Manufacturer=MuRata, Supplier Part Number 1=490-10698-1-ND, TempCo=X7R, Tolerance_%=10%, Value1=Unknown, Value2=25V, ValueDisplayed=0.1uF
C20: library part CMP-0006462-2, "CAP, CERM, 3.3 pF, 50 V, +/- 5%, C0G/NP0, 0402", Cap_Case=0402, Manufacturer=MuRata, Supplier Part Number 1=81-GRM1555C1H3R3CA1D, TempCo=C0G/NP0, Tolerance_%=5%, Value1=Unknown, Value2=50V, ValueDisplayed=3.3pF
C21: library part CMP-0006365-2, "CAP, CERM, 27 pF, 50 V, +/- 5%, C0G/NP0, 0402", Cap_Case=0402, Manufacturer=MuRata, TempCo=C0G/NP0, Tolerance_%=5%, Value1=Unknown, Value2=50V, ValueDisplayed=27pF
C22: library part C2012JB1V226M125AC, "CAP, CERM, 10 µF, 35 V, +/- 10%, X6S, 0805", Cap_Case=0805, Manufacturer=TDK, Supplier Part Number 1=490-10504-1-ND, TempCo=X6S, Tolerance_%=20, Value1=Unknown, Value2=35V, ValueDisplayed=10µF
C23: library part CMP-0006683-2, "CAP, CERM, 2200 pF, 50 V, +/- 10%, X7R, 0402", Cap_Case=0402, Manufacturer=MuRata, Supplier Part Number 1=490-1305-1-ND, TempCo=X7R, Tolerance_%=10%, Value1=Unknown, Value2=50V, ValueDisplayed=2200pF
C24: library part CMP-0006441-2, "CAP, CERM, 24 pF, 50 V, +/- 5%, C0G/NP0, 0402", Cap_Case=0402, Manufacturer=MuRata, Supplier Part Number 1=81-GRM1555C1H240JA1D, TempCo=C0G/NP0, Tolerance_%=5%, Value1=Unknown, Value2=50V, ValueDisplayed=24pF
C25: library part CMP-0006681-2, "CAP, CERM, 0.018 uF, 50 V, +/- 10%, X7R, 0402", Cap_Case=0402, Manufacturer=MuRata, Supplier Part Number 1=GRM155R71H183KA12D-ND, TempCo=X7R, Tolerance_%=10%, Value1=Unknown, Value2=50V, ValueDisplayed=0.018uF
C27: library part CMP-0006692-2, "CAP, CERM, 4700 pF, 50 V, +/- 10%, X7R, 0402", Cap_Case=0402, Manufacturer=MuRata, Supplier Part Number 1=490-1308-1-ND, TempCo=X7R, Tolerance_%=10%, Value1=Unknown, Value2=50V, ValueDisplayed=4700pF
C29: library part CMP-0008310-1, "CAP, CERM, 10 uF, 35 V, +/- 10%, X5R, 0805", Cap_Case=0805, Manufacturer=MuRata, Supplier Part Number 1=490-10514-1-ND, TempCo=X5R, Tolerance_%=10%, Value1=Unknown, Value2=35V, ValueDisplayed=10uF
C30: "CAP, CERM, 0.27 µF, 6.3 V, +/- 10%, X5R, 0402", Cap_Case=0402, Manufacturer=MuRata, Supplier Part Number 1=GRM155R60J274KE01D-ND, TempCo=X5R, Tolerance_%=10, Value1=Unknown, Value2=6.3V, ValueDisplayed=0.27µF
C31 C32: "CAP, CERM, 0.1 µF, 16 V, +/- 10%, X7R, 0402", Cap_Case=0402, Manufacturer=MuRata, Supplier Part Number 1=490-3261-1-ND, TempCo=X7R, Tolerance_%=10, Value1=Unknown, Value2=16V, ValueDisplayed=0.1µF
C33 C34: "CAP, CERM, 470 pF, 50 V, +/- 10%, X7R, 0402", Cap_Case=0402, Manufacturer=MuRata, Supplier Part Number 1=490-1300-1-ND, TempCo=X7R, Tolerance_%=10, Value1=Unknown, Value2=50V, ValueDisplayed=470pF
C35 C38 C39 C40: library part CMP-0009224-2, "CAP, CERM, 22 uF, 25 V, +/- 10%, X7R, 1210", Cap_Case=1210, Manufacturer=MuRata, Supplier Part Number 1=490-5313-1-ND, TempCo=X7R, Tolerance_%=10%, Value1=Unknown, Value2=25V, ValueDisplayed=22uF
C36: library part CMP-0008995-2, "CAP, CERM, 0.22 uF, 50 V, +/- 10%, X7R, 1206", Cap_Case=1206, Manufacturer=MuRata, Supplier Part Number 1=GRM31MR71H224KA01L-ND, TempCo=X7R, Tolerance_%=10%, Value1=Unknown, Value2=50V, ValueDisplayed=0.22uF
C37: library part CMP-0081668-2, "CAP, Aluminum Polymer, 680 µF, 25 V,+/- 20%, 0.29256 ohm, TH", Cap_Case=10x12mm, Manufacturer="Illinois Capacitor", Supplier Part Number 1=1572-1754-ND, Tolerance_%=20%, Value1="0.29256 ohm", Value2=25V, ValueDisplayed=680µF
C41: library part CMP-0008236-2, "CAP, CERM, 100 pF, 250 V, +/- 5%, C0G/NP0, 0805", Cap_Case=0805, Manufacturer=MuRata, Supplier Part Number 1=490-5542-1-ND, TempCo=C0G/NP0, Tolerance_%=5%, Value1=Unknown, Value2=250V, ValueDisplayed=100pF
C42: library part CMP-0008342-2, "CAP, CERM, 2.2 uF, 25 V, +/- 10%, X7R, 0805", Cap_Case=0805, Manufacturer=MuRata, Supplier Part Number 1=490-3331-1-ND, TempCo=X7R, Tolerance_%=10%, Value1="0.005 ohm", Value2=25V, ValueDisplayed=2.2uF
C44: library part CMP-0008487-2, "CAP, CERM, 0.1 uF, 100 V, +/- 5%, X7R, 1206", Cap_Case=1206, Manufacturer=AVX, Supplier Part Number 1=478-3785-1-ND, TempCo=X7R, Tolerance_%=5%, Value1="0.037 ohm", Value2=100V, ValueDisplayed=0.1uF
C100: library part CMP-0006420-2, "CAP, CERM, 15 pF, 50 V, +/- 5%, C0G/NP0, 0402", Cap_Case=0402, Manufacturer=MuRata, Supplier Part Number 1=81-GRM1555C1H150JA1D, TempCo=C0G/NP0, Tolerance_%=5%, Value1=Unknown, Value2=50V, ValueDisplayed=15pF
C101: library part CMP-0006440-2, "CAP, CERM, 220 pF, 50 V, +/- 5%, C0G/NP0, 0402", Cap_Case=0402, Manufacturer=MuRata, Supplier Part Number 1=490-1293-1-ND, TempCo=C0G/NP0, Tolerance_%=5%, Value1=Unknown, Value2=50V, ValueDisplayed=220pF
D1: library part CMP-0005829-1, "Diode, Zener, 10 V, 200 mW, SOD-323", Manufacturer="Diodes Inc.", Power_W=200mW, Supplier Part Number 1=MMSZ5240BS-FDICT-ND, Value1=0.2W
D2: library part CMP-0029162-1, "Diode, Ultrafast, 600 V, 1 A, AEC-Q101, SMAF", Manufacturer="Fairchild Semiconductor", Supplier Part Number 1=ES1JAFCT-ND, Value1=1A, Value2=1.7V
